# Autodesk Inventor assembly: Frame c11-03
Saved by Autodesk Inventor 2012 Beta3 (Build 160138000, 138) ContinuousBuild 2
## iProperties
Created: 2011-01
Part Number: Frame c11-03
Document SubType Name: Assembly
Designer: Beta-8540w
_FrameDoc: Frame Assembly
_Version: 15.0.0
Author: Beta-8540w
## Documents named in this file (18)
- C:\Inventor 2012 Essentials\Assemblies\Chapter 11\Frame\Frame c11-03.iam
- C:\Inventor 2012 Essentials\Assemblies\Chapter 11\Frame\Skeleton-c11-03.ipt
- C:\Inventor 2012 Essentials\Assemblies\Chapter 11\Frame\ANSI 3x3x3_16 00000007.ipt
- ANSI 3x3x3_16 00000007.ipt
- C:\Inventor 2012 Essentials\Assemblies\Chapter 11\Frame\ANSI 3x3x3_16 00000008.ipt
- ANSI 3x3x3_16 00000008.ipt
- C:\Inventor 2012 Essentials\Assemblies\Chapter 11\Frame\ANSI 3x3x3_16 00000009.ipt
- ANSI 3x3x3_16 00000009.ipt
- C:\Inventor 2012 Essentials\Assemblies\Chapter 11\Frame\ANSI 3x3x3_16 00000010.ipt
- ANSI 3x3x3_16 00000010.ipt
- C:\Inventor 2012 Essentials\Assemblies\Chapter 11\Frame\ANSI 3x3x3_16 00000012.ipt
- ANSI 3x3x3_16 00000012.ipt
- C:\Inventor 2012 Essentials\Assemblies\Chapter 11\Frame\ANSI L 1.5 x 1.5 x 3_16 00000013.ipt
- ANSI L 1.5 x 1.5 x 3_16 00000013.ipt
- C:\Inventor 2012 Essentials\Assemblies\Chapter 11\Frame\ANSI L 1.5 x 1.5 x 3_16 00000014.ipt
- ANSI L 1.5 x 1.5 x 3_16 00000014.ipt
- C:\Inventor 2012 Essentials\Assemblies\Chapter 11\Frame\ANSI 3x3x3_16 00000053.ipt
- ANSI 3x3x3_16 00000011.ipt
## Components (9 placed, 9 different names)
1. Frame Reference Model
2. ANSI 3x3x3_16 00000007:1
3. ANSI 3x3x3_16 00000008:1
4. ANSI 3x3x3_16 00000009:1
5. ANSI 3x3x3_16 00000010:1
6. ANSI 3x3x3_16 00000012:1
7. ANSI L 1.5 x 1.5 x 3_16 00000013:1
8. ANSI L 1.5 x 1.5 x 3_16 00000014:1
9. ANSI 3x3x3_16 00000011:1
